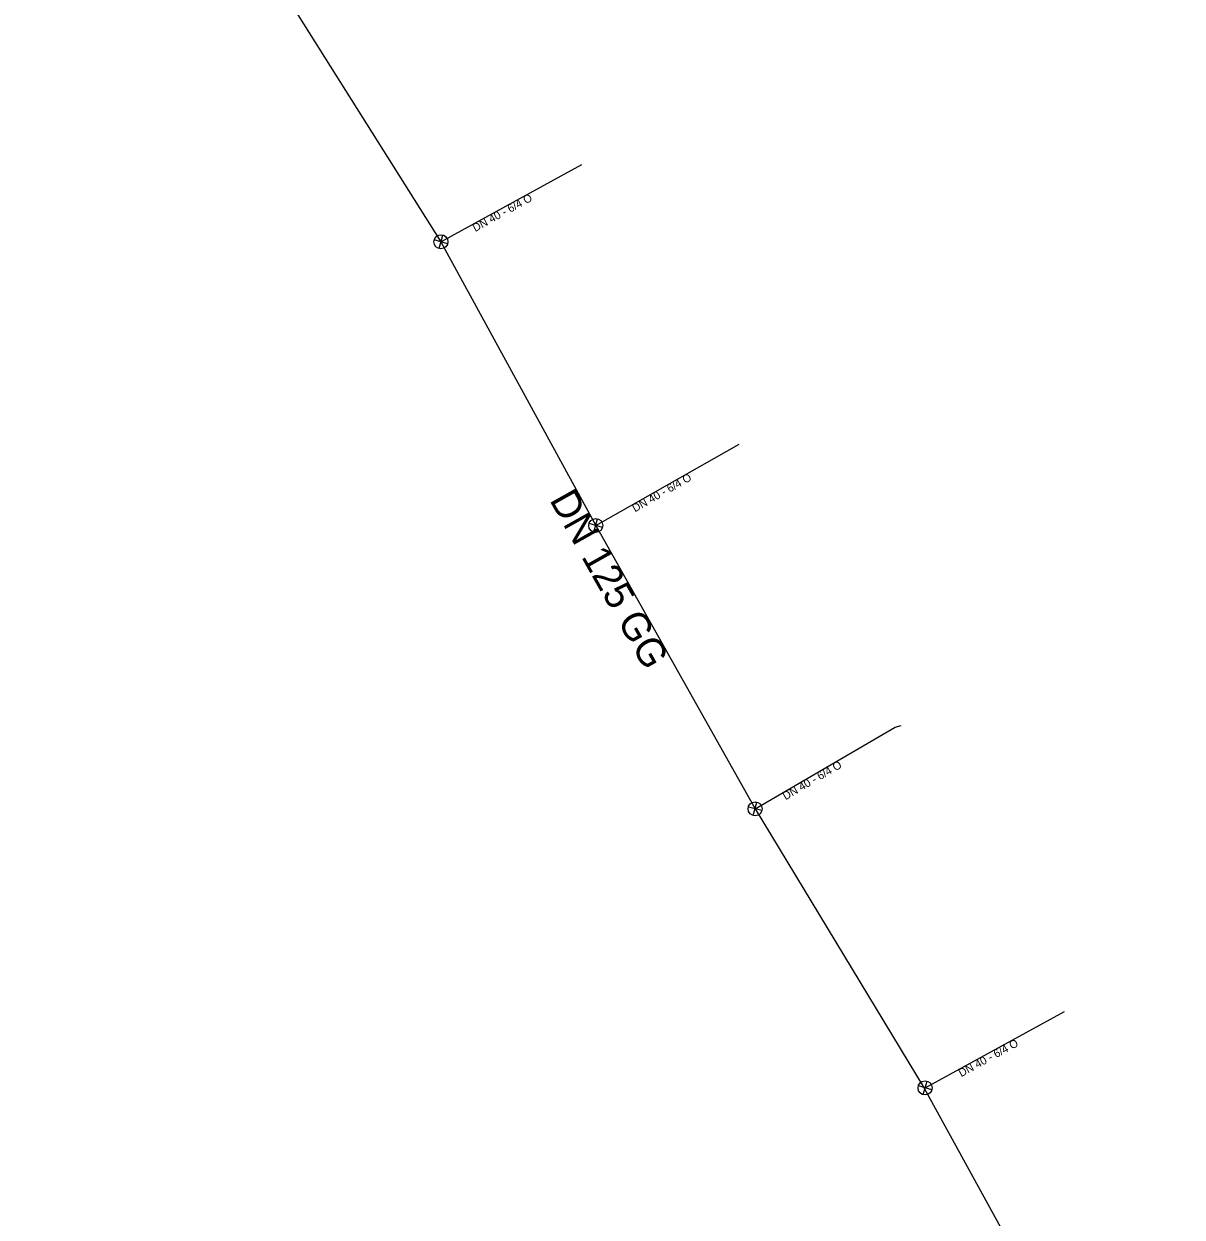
# Model space of a CAD drawing. Extents: x -443562 to -443270, y -1122830 to -1122511.
# Drawn here: x -443508.6 to -443442.8, y -1122743.1 to -1122675.2 of the extents above; entities that cross this region are included whole.
import ezdxf

# ---------------------------------------------------------------- set-up
doc = ezdxf.new("R2010")
doc.units = 0
for name, color, linetype in [('_pripojka_priblizne_', 7, 'Continuous'), ('_voda_smvak_prevzato_z_dokumentace_', 7, 'Continuous'), ('Default', 7, 'Continuous'), ('MoLevel 32', 7, 'Continuous'), ('MoLevel 46', 7, 'Continuous'), ('MoLevel 53', 7, 'Continuous')]:
    doc.layers.add(name, color=color, linetype=linetype)

# ---------------------------------------------------------------- blocks, each defined once
blk = doc.blocks.new('_uzaver_pripojka_')
at = {"layer": 'Default'}
for p, q in [((-0.000035, -0.000035), (0.000035, 0.000035)), ((0.000035, -0.000035), (-0.000035, 0.000035))]:
    blk.add_line(p, q, dxfattribs=at)
for radius in [0.00005, 0.0000025]:
    blk.add_circle((0, 0), radius, dxfattribs=at)

msp = doc.modelspace()

# ---------------------------------------------------------------- linework, layer by layer
at = {"layer": '_pripojka_priblizne_'}
for p, q in [((-443484.93, -1122687.61), (-443476.929, -1122683.206)), ((-443476.13, -1122703.74), (-443467.99, -1122699.11))]:
    msp.add_line(p, q, dxfattribs=at)
for points in [[(-443467.08, -1122719.85), (-443459.11, -1122715.21), (-443458.784, -1122715.103)], [(-443457.463, -1122735.742), (-443457.42, -1122735.72), (-443449.488, -1122731.378)]]:
    msp.add_lwpolyline(points, dxfattribs=at)
at = {"layer": '_voda_smvak_prevzato_z_dokumentace_'}
msp.add_lwpolyline([(-443508.63, -1122645.88), (-443495.13, -1122671.4), (-443484.93, -1122687.61), (-443476.13, -1122703.74), (-443467.08, -1122719.85), (-443457.463, -1122735.742), (-443449.31, -1122750.61), (-443442.813, -1122761.691)], dxfattribs=at)

# ---------------------------------------------------------------- block references
at = {"layer": 'MoLevel 53'}
for p, xscale, yscale, rotation in [((-443484.93, -1122687.61), 8000, 7999.999999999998, 28.829555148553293), ((-443476.13, -1122703.74), 7999.999999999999, 7999.999999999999, 29.631048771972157), ((-443467.08, -1122719.85), 7999.999999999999, 7999.999999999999, 30.207244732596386), ((-443457.42, -1122735.72), 8000, 7999.999999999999, 28.693170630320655)]:
    msp.add_blockref('_uzaver_pripojka_', p, dxfattribs=dict(at, xscale=xscale, yscale=yscale, rotation=rotation))

# ---------------------------------------------------------------- texts
at = {"layer": 'MoLevel 32'}
for rotation, p in [(28.82956, (-443482.981, -1122687.057)), (29.63105, (-443473.904, -1122702.998)), (30.20724, (-443465.349, -1122719.369)), (28.69512, (-443455.366, -1122735.114))]:
    msp.add_text('DN 40 - 6/4 O', height=0.455, rotation=rotation, dxfattribs=at).set_placement(p)
at = {"layer": 'MoLevel 46'}
msp.add_text('DN 125 GG', height=1.6049, rotation=299.32567, dxfattribs=at).set_placement((-443478.789, -1122702.283))

doc.saveas('drawing.dxf')
